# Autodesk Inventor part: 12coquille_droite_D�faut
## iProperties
Created: 2011-01
Part Number: 12coquille_droite_D�faut
Document SubType Name: Modeling
Designer: eric
Density: 1 g/cm^3
Mass: 223.119 g
Surface Area: 1202.09 cm^2
Volume: 223.119 cm^3
Author: eric
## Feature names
1. Base1
